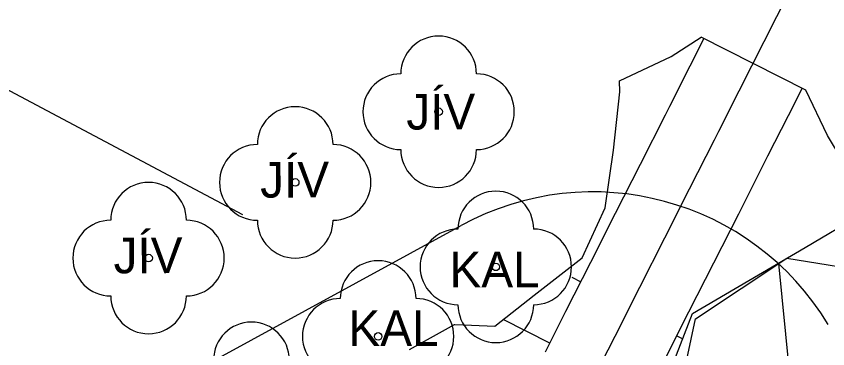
# Model space of a CAD drawing. Extents: x -564037 to -563722, y -1163561 to -1163412.
# Drawn here: x -563870.9 to -563856.15, y -1163489.75 to -1163483.71 of the extents above; entities that cross this region are included whole.
import ezdxf

# ---------------------------------------------------------------- set-up
doc = ezdxf.new("R2010")
doc.units = 0
for name, color, linetype in [('5', 7, 'Continuous'), ('Default', 7, 'Continuous'), ('Line', 7, 'Continuous'), ('Vrstva 1', 7, 'Continuous'), ('Vrstva 2', 7, 'Continuous')]:
    doc.layers.add(name, color=color, linetype=linetype)

msp = doc.modelspace()

# ---------------------------------------------------------------- linework, layer by layer
for points in [[(-563860.387, -1163490.259), (-563860.015, -1163489.524), (-563859.563, -1163488.631), (-563859.112, -1163487.739), (-563858.66, -1163486.847), (-563858.209, -1163485.954), (-563858.129, -1163485.798), (-563857.757, -1163485.062), (-563856.157, -1163481.899)], [(-563866.782, -1163487.32), (-563875.054, -1163482.917), (-563879.887, -1163483.398)], [(-563861.279, -1163489.807), (-563860.907, -1163489.072), (-563860.456, -1163488.18), (-563860.004, -1163487.288), (-563859.553, -1163486.395), (-563859.101, -1163485.503), (-563859.022, -1163485.346), (-563858.65, -1163484.611), (-563858.399, -1163484.116)], [(-563860.615, -1163488.099), (-563860.193, -1163487.192), (-563860.044, -1163486.146), (-563859.928, -1163485.085), (-563859.936, -1163484.884), (-563858.994, -1163484.437), (-563858.449, -1163484.09)], [(-563858.608, -1163489.115), (-563857.583, -1163488.513), (-563856.558, -1163487.911), (-563855.533, -1163487.308), (-563855.353, -1163487.203), (-563856.153, -1163485.874), (-563856.548, -1163485.052), (-563858.449, -1163484.09)], [(-563859.123, -1163489.975), (-563858.671, -1163489.083), (-563858.22, -1163488.191), (-563857.768, -1163487.298), (-563857.317, -1163486.406), (-563857.237, -1163486.249), (-563856.865, -1163485.514), (-563856.615, -1163485.019)], [(-563863.754, -1163489.765), (-563863.59, -1163489.674), (-563863.426, -1163489.583), (-563863.262, -1163489.493), (-563863.097, -1163489.403), (-563862.931, -1163489.313), (-563862.926, -1163489.31), (-563862.625, -1163489.323), (-563862.199, -1163489.342), (-563861.486, -1163488.779), (-563860.615, -1163488.099)], [(-563858.97, -1163490.052), (-563858.608, -1163489.115)]]:
    msp.add_lwpolyline(points)
at = {"layer": '5'}
msp.add_line((-563897.15, -1163506.247), (-563862.812, -1163487.513), dxfattribs=at)
msp.add_arc((-563860.417, -1163491.902), 5, 31.1947, 118.6163, dxfattribs=at)
at = {"layer": 'Default'}
msp.add_lwpolyline([(-563861.871, -1163501.708), (-563861.355, -1163499.743), (-563861.175, -1163499.057), (-563860.744, -1163497.818), (-563860.132, -1163496.055), (-563859.88, -1163495.331), (-563859.856, -1163495.261), (-563859.628, -1163494.247), (-563858.554, -1163489.211), (-563856.89, -1163488.106), (-563853.44, -1163488.662), (-563853.44, -1163488.662), (-563852.435, -1163488.408), (-563849.66, -1163490.902), (-563849.248, -1163491.704), (-563847.479, -1163495.149), (-563847.069, -1163497.206), (-563847.056, -1163497.268), (-563846.963, -1163497.738), (-563846.685, -1163499.13), (-563846.607, -1163499.521), (-563845.777, -1163503.681)], dxfattribs=at)
at = {"layer": 'Line'}
for p, q in [((-563856.587, -1163492.721), (-563857.038, -1163488.204)), ((-563860.8, -1163488.455), (-563860.637, -1163488.538)), ((-563861.201, -1163489.653), (-563862.049, -1163489.224)), ((-563858.893, -1163489.521), (-563858.785, -1163489.575))]:
    msp.add_line(p, q, dxfattribs=at)
at = {"layer": 'Vrstva 2'}
for centre in [(-563863.222, -1163485.444), (-563865.829, -1163486.729), (-563868.494, -1163488.105), (-563862.182, -1163488.265), (-563864.321, -1163489.529)]:
    msp.add_circle(centre, 0.0688, dxfattribs=at)
for centre, start, end in [((-563863.222, -1163484.756), 0, 180), ((-563863.91, -1163485.444), 90, 270), ((-563862.534, -1163485.444), 270, 90), ((-563865.829, -1163486.041), 0, 180), ((-563866.517, -1163486.729), 90, 270), ((-563865.141, -1163486.729), 270, 90), ((-563863.222, -1163486.132), 180, 0), ((-563868.494, -1163487.417), 0, 180), ((-563862.182, -1163487.577), 0, 180), ((-563869.182, -1163488.105), 90, 270), ((-563867.807, -1163488.105), 270, 90), ((-563865.829, -1163487.417), 180, 0), ((-563862.87, -1163488.265), 90, 270), ((-563861.495, -1163488.265), 270, 90), ((-563864.321, -1163488.841), 0, 180), ((-563868.494, -1163488.793), 180, 0), ((-563865.009, -1163489.529), 90, 270), ((-563863.633, -1163489.529), 270, 90), ((-563862.182, -1163488.953), 180, 0), ((-563866.624, -1163489.957), 0, 180)]:
    msp.add_arc(centre, 0.688, start, end, dxfattribs=at)

# ---------------------------------------------------------------- texts
at = {"layer": 'Vrstva 1'}
for s, p in [('JÍV', (-563863.808, -1163485.769)), ('JÍV', (-563866.464, -1163487.006)), ('JÍV', (-563869.129, -1163488.382)), ('KAL', (-563863.024, -1163488.639)), ('KAL', (-563864.861, -1163489.706))]:
    msp.add_text(s, height=0.648, rotation=0.1546, dxfattribs=at).set_placement(p)

doc.saveas('drawing.dxf')
